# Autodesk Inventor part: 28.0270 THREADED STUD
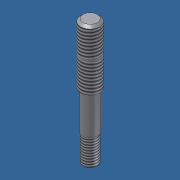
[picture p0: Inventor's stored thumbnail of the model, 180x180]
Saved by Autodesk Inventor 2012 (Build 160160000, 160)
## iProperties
Created: 2007-06
Part Number: 28.0270 THREADED STUD
Material: Stainless Steel
Document SubType Name: Modeling
Designer: Andy Moles
Mass: 16.7325 g
Surface Area: 12.4187 cm^2
Volume: 2.07085 cm^3
Density: 8.08 g/cm^3
Author: Andy Moles
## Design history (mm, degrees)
sketch "Sketch1"
  geometry: C1 r 3 at (0, 0); 1 further point
  constraints: 1 centre point, 1 coincident
  dimensions: "d0" = 6 diameter of C1
extrude "Extrusion1" new body sketch "Sketch1" distance "d1" = 11; taper "d2" = 0 deg
sketch "Sketch2"
  geometry: C1 r 3 at (0, 0) reference; C2 r 3.2 at (0, 0)
  constraints: 1 centre point, 1 coincident
  dimensions: "d3" = 6.4 diameter of C2
extrude "Extrusion2" join sketch "Sketch2" distance "d4" = 16; taper "d5" = 0 deg
sketch "Sketch3"
  geometry: C1 r 3.2 at (0, 0) reference; C2 r 4 at (0, 0)
  constraints: 1 centre point, 1 coincident
  dimensions: "d6" = 8 diameter of C2
extrude "Extrusion3" join sketch "Sketch3" distance "d7" = 25; taper "d8" = 0 deg
thread "Thread1" dims "d9" = 10, "d10" = 0
thread "Thread2" dims "d11" = 12, "d12" = 13
thread "Thread3" dims "d13" = 12, "d14" = 0
chamfer "Chamfer1" distance "d15" = 1; stored, may be unused: second distance "d16" = 2, angle "d17" = 45 deg
body "Solid1"
